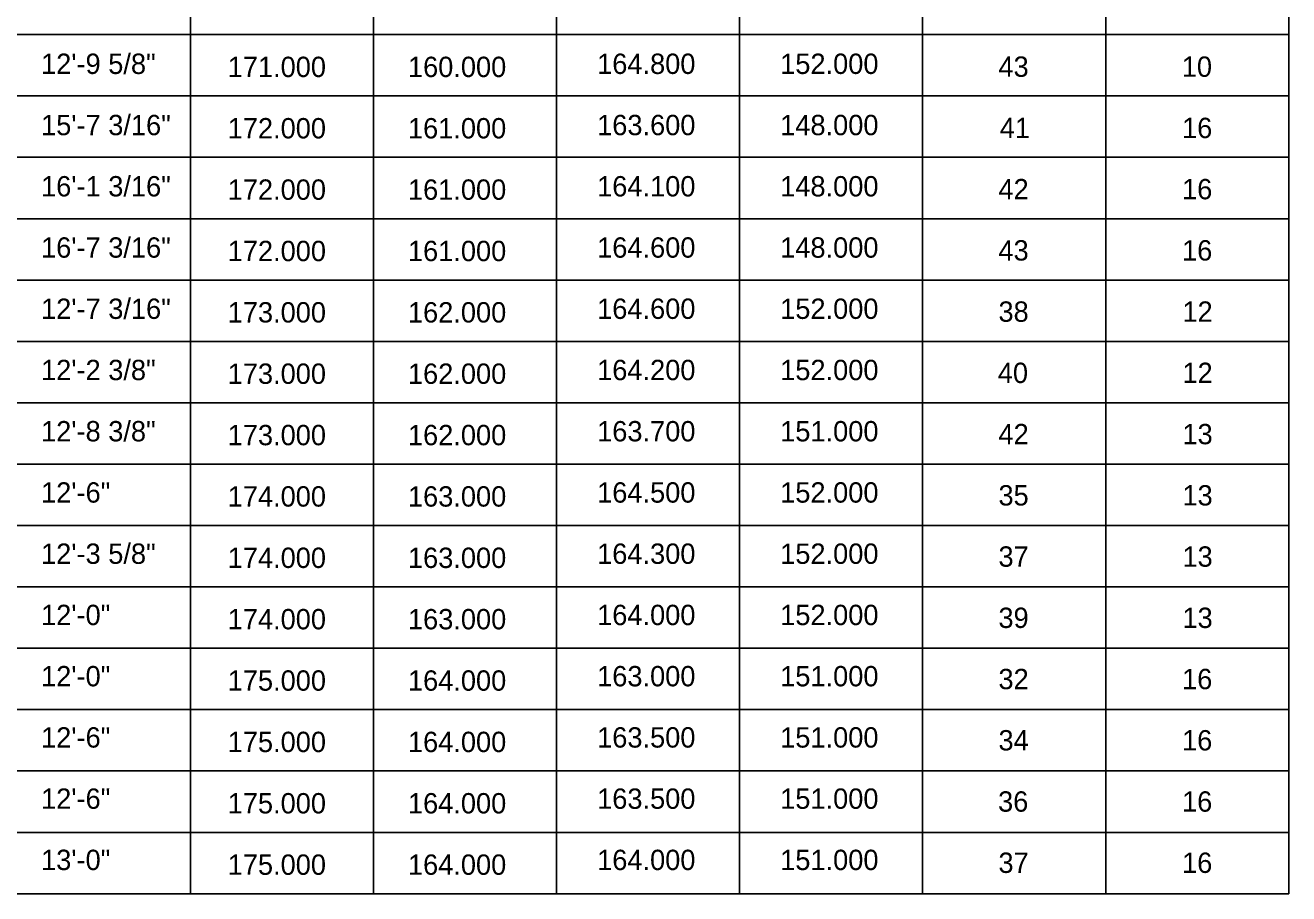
# Model space of a CAD drawing. Extents: x -133.1 to -97, y -1.7 to 20.3.
# Drawn here: x -111.15 to -103.39, y 4 to 9.34 of the extents above; entities that cross this region are included whole.
import ezdxf

# ---------------------------------------------------------------- set-up
doc = ezdxf.new("R2010")
doc.units = 0
doc.layers.add('BR_TABLE LINES', color=7, linetype='Continuous')
doc.layers.add('BR_TEXT', color=7, linetype='Continuous')

msp = doc.modelspace()

# ---------------------------------------------------------------- linework, layer by layer
at = {"layer": 'BR_TABLE LINES'}
for p, q in [((-103.3871, 4.001), (-103.3871, 19.2534)), ((-110.1371, 4.001), (-110.1371, 18.7534)), ((-109.0121, 4.001), (-109.0121, 18.7534)), ((-107.8871, 4.001), (-107.8871, 18.7534)), ((-106.7621, 4.001), (-106.7621, 18.7534)), ((-105.6371, 4.001), (-105.6371, 18.7534)), ((-104.5121, 4.001), (-104.5121, 18.7534)), ((-115.482, 9.2796), (-103.3871, 9.2796)), ((-115.482, 8.9025), (-103.3871, 8.9025)), ((-115.482, 8.5255), (-103.3871, 8.5255)), ((-115.482, 8.1485), (-103.3871, 8.1485)), ((-115.482, 7.7714), (-103.3871, 7.7714)), ((-115.482, 7.3944), (-103.3871, 7.3944)), ((-115.482, 7.0174), (-103.3871, 7.0173)), ((-115.482, 6.6403), (-103.3871, 6.6403)), ((-115.482, 6.2633), (-103.3871, 6.2633)), ((-115.482, 5.8862), (-103.3871, 5.8862)), ((-115.482, 5.5092), (-103.3871, 5.5092)), ((-115.482, 5.1322), (-103.3871, 5.1322)), ((-115.482, 4.7551), (-103.3871, 4.7551)), ((-115.482, 4.3781), (-103.3871, 4.3781)), ((-115.482, 4.001), (-103.3871, 4.001))]:
    msp.add_line(p, q, dxfattribs=at)

# ---------------------------------------------------------------- texts
at = {"layer": 'BR_TEXT'}
for s, p in [('12\'-9 5/8"', (-111.0553, 9.0377)), ('164.800', (-107.6377, 9.0377)), ('152.000', (-106.5127, 9.0377)), ('171.000', (-109.9083, 9.0187)), ('160.000', (-108.8004, 9.0187)), ('43', (-105.1712, 9.0201)), ('10', (-104.0444, 9.0201)), ('15\'-7 3/16"', (-111.0553, 8.6614)), ('163.600', (-107.6377, 8.6614)), ('148.000', (-106.5127, 8.6614)), ('172.000', (-109.9083, 8.6417)), ('161.000', (-108.8004, 8.6417)), ('41', (-105.163, 8.6438)), ('16', (-104.0428, 8.6438)), ('16\'-1 3/16"', (-111.0553, 8.2852)), ('172.000', (-109.9083, 8.2647)), ('161.000', (-108.8004, 8.2647)), ('164.100', (-107.6377, 8.2852)), ('148.000', (-106.5127, 8.2852)), ('42', (-105.1712, 8.2676)), ('16', (-104.0428, 8.2676)), ('16\'-7 3/16"', (-111.0553, 7.9089)), ('172.000', (-109.9083, 7.8876)), ('161.000', (-108.8004, 7.8876)), ('164.600', (-107.6377, 7.9089)), ('148.000', (-106.5127, 7.9089)), ('43', (-105.1712, 7.8913)), ('16', (-104.0428, 7.8913)), ('12\'-7 3/16"', (-111.0553, 7.5327)), ('173.000', (-109.9083, 7.5106)), ('162.000', (-108.8004, 7.5106)), ('164.600', (-107.6377, 7.5327)), ('152.000', (-106.5127, 7.5327)), ('38', (-105.1712, 7.5151)), ('12', (-104.0404, 7.5151)), ('12\'-2 3/8"', (-111.0553, 7.1564)), ('173.000', (-109.9083, 7.1336)), ('162.000', (-108.8004, 7.1336)), ('164.200', (-107.6377, 7.1564)), ('152.000', (-106.5127, 7.1564)), ('40', (-105.1752, 7.1388)), ('12', (-104.0404, 7.1388)), ('12\'-8 3/8"', (-111.0553, 6.7802)), ('173.000', (-109.9083, 6.7565)), ('162.000', (-108.8004, 6.7565)), ('163.700', (-107.6377, 6.7802)), ('151.000', (-106.5127, 6.7802)), ('42', (-105.1712, 6.7626)), ('13', (-104.0404, 6.7626)), ('12\'-6"', (-111.0553, 6.4039)), ('164.500', (-107.6377, 6.4039)), ('152.000', (-106.5127, 6.4039)), ('174.000', (-109.9083, 6.3795)), ('163.000', (-108.8004, 6.3795)), ('35', (-105.1712, 6.3863)), ('13', (-104.0404, 6.3863)), ('12\'-3 5/8"', (-111.0553, 6.0277)), ('164.300', (-107.6377, 6.0277)), ('152.000', (-106.5127, 6.0277)), ('37', (-105.1712, 6.0101)), ('13', (-104.0404, 6.0101)), ('174.000', (-109.9083, 6.0024)), ('163.000', (-108.8004, 6.0024)), ('12\'-0"', (-111.0553, 5.6514)), ('174.000', (-109.9083, 5.6254)), ('163.000', (-108.8004, 5.6254)), ('164.000', (-107.6377, 5.6514)), ('152.000', (-106.5127, 5.6514)), ('39', (-105.1712, 5.6338)), ('13', (-104.0404, 5.6338)), ('12\'-0"', (-111.0553, 5.2752)), ('175.000', (-109.9083, 5.2484)), ('164.000', (-108.8004, 5.2484)), ('163.000', (-107.6377, 5.2752)), ('151.000', (-106.5127, 5.2752)), ('32', (-105.1712, 5.2576)), ('16', (-104.0428, 5.2576)), ('12\'-6"', (-111.0553, 4.8989)), ('175.000', (-109.9083, 4.8713)), ('164.000', (-108.8004, 4.8713)), ('163.500', (-107.6377, 4.8989)), ('151.000', (-106.5127, 4.8989)), ('34', (-105.1712, 4.8813)), ('16', (-104.0428, 4.8813)), ('12\'-6"', (-111.0553, 4.5227)), ('175.000', (-109.9083, 4.4943)), ('164.000', (-108.8004, 4.4943)), ('163.500', (-107.6377, 4.5227)), ('151.000', (-106.5127, 4.5227)), ('36', (-105.1736, 4.5051)), ('16', (-104.0428, 4.5051)), ('13\'-0"', (-111.0553, 4.1464)), ('164.000', (-107.6377, 4.1464)), ('151.000', (-106.5127, 4.1464)), ('175.000', (-109.9083, 4.1172)), ('164.000', (-108.8004, 4.1172)), ('37', (-105.1712, 4.1288)), ('16', (-104.0428, 4.1288))]:
    msp.add_text(s, height=0.125, rotation=359.99995, dxfattribs=at).set_placement(p)

doc.saveas('drawing.dxf')
